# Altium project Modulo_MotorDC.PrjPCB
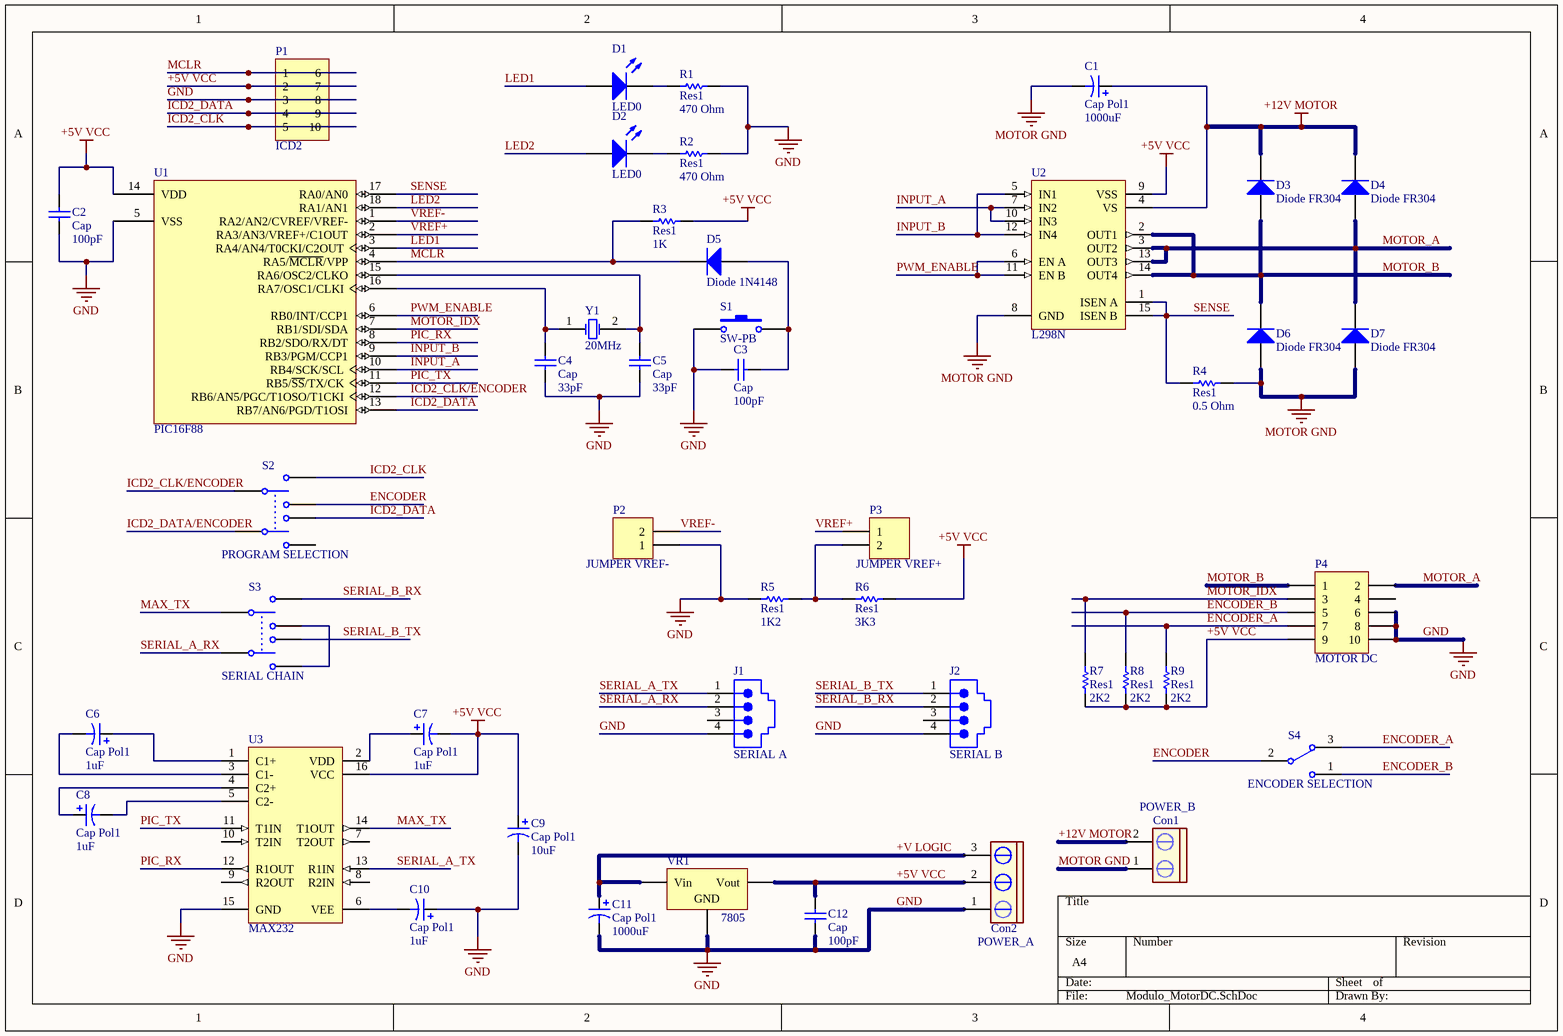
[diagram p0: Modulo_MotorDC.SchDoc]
1 sheet, 45 parts. Net scope: global (net labels, ports and power ports of the same name join across sheets).
Board file: Modulo_MotorDC.PcbDoc

## Sheet Modulo_MotorDC.SchDoc
size A4

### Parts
C1  Cap Pol1  value 1000uF  [RB5-10.5]
C2  Cap  value 100pF  [CAPR2.54-5.1x3.2]
C3  Cap  value 100pF  [CAPR2.54-5.1x3.2]
C4  Cap  value 33pF  [CAPR2.54-5.1x3.2]
C5  Cap  value 33pF  [CAPR2.54-5.1x3.2]
C6  Cap Pol1  value 1uF  [CAPPR2-5x6.8]
C7  Cap Pol1  value 1uF  [CAPPR2-5x6.8]
C8  Cap Pol1  value 1uF  [CAPPR2-5x6.8]
C9  Cap Pol1  value 10uF  [CAPPR2-5x6.8]
C10  Cap Pol1  value 1uF  [CAPPR2-5x6.8]
C11  Cap Pol1  value 1000uF  [RB5-10.5]
C12  Cap  value 100pF  [CAPR2.54-5.1x3.2]
Con1  POWER_B  [My_CN2]
Con2  POWER_A  [My_CN3]
D1  LED0  [LED-0]
D2  LED0  [LED-0]
D3  Diode FR304  [DIO18.84-9.6x5.6]
D4  Diode FR304  [DIO18.84-9.6x5.6]
D5  Diode 1N4148  [DIO7.1-3.9x1.9]
D6  Diode FR304  [DIO18.84-9.6x5.6]
D7  Diode FR304  [DIO18.84-9.6x5.6]
J1  SERIAL A  [15-43-6245]
J2  SERIAL B  [15-43-6245]
P1  ICD2  [HEADER10_5x2_B]
P2  JUMPER VREF-  [HDR1X2]
P3  JUMPER VREF+  [HDR1X2]
P4  MOTOR DC  [HEADER10_5x2_A]
R1  Res1  value 470 Ohm  [AXIAL-0.3]
R2  Res1  value 470 Ohm  [AXIAL-0.3]
R3  Res1  value 1K  [AXIAL-0.3]
R4  Res1  value 0.5 Ohm  [AXIAL-0.3]
R5  Res1  value 1K2  [AXIAL-0.3]
R6  Res1  value 3K3  [AXIAL-0.3]
R7  Res1  value 2K2  [AXIAL-0.3]
R8  Res1  value 2K2  [AXIAL-0.3]
R9  Res1  value 2K2  [AXIAL-0.3]
S1  SW-PB  [TS-063]
S2  PROGRAM SELECTION  [LD-202mini]
S3  SERIAL CHAIN  [LD-202mini]
S4  ENCODER SELECTION  [LD-202mini]
U1  PIC16F88  [PDIP300-P18]
U2  L298N  [Multiwatt15V]
U3  MAX232  [PE16A]
VR1  7805  [My_TO-220]
Y1  20MHz  [My_Crystal]

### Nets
+5V VCC: C2.2 C7.2 C9.1 C12.2 Con2.2 P1.2 P1.7 P4.9 R3.2 R6.2 R7.1 R8.1 R9.1 U1.14(VDD) U2.9(VSS) U3.16(VCC) VR1.3(Vout)
+12V MOTOR: C1.1 Con1.2 D3.2(K) D4.2(K) U2.4(VS)
GND: C2.1 C3.1 C4.1 C5.1 C9.2 C10.1 C11.2 C12.1 Con2.1 J1.4 J2.4 P1.3 P1.8 P2.1 P4.6 P4.8 P4.10 R1.2 R2.2 R5.1 S1.1 U1.5(VSS) U3.15(GND) VR1.2(GND)
MOTOR GND: C1.2 Con1.1 D6.1(A) D7.1(A) R4.2 U2.8(GND)
+V LOGIC: C11.1 Con2.3 VR1.1(Vin)
ENCODER: S2.3 S4.2
ENCODER_A: P4.7 R9.2 S4.3
ENCODER_B: P4.5 R8.2 S4.1
ICD2_CLK: P1.5 P1.10 S2.2
ICD2_CLK/ENCODER: S2.1 U1.12(RB6/AN5/PGC/T1OSO/T1CKI)
ICD2_DATA: P1.4 P1.9 S2.5 U1.13(RB7/AN6/PGD/T1OSI)
ICD2_DATA/ENCODER: S2.4
INPUT_A: U1.10(RB4/SCK/SCL) U2.7(IN2) U2.10(IN3)
INPUT_B: U1.9(RB3/PGM/CCP1) U2.5(IN1) U2.12(IN4)
LED1: D1.1(A) U1.3(RA4/AN4/T0CKI/C2OUT)
LED2: D2.1(A) U1.18(RA1/AN1)
MAX_TX: S3.1 U3.14(T1OUT)
MCLR: D5.2(K) P1.1 P1.6 R3.1 U1.4(RA5/~{MCLR}/VPP)
MOTOR_A: D4.1(A) D7.2(K) P4.2 U2.3(OUT2) U2.13(OUT3)
MOTOR_B: D3.1(A) D6.2(K) P4.1 U2.2(OUT1) U2.14(OUT4)
MOTOR_IDX: P4.3 R7.2 U1.7(RB1/SDI/SDA)
PIC_RX: U1.8(RB2/SDO/RX/DT) U3.12(R1OUT)
PIC_TX: U1.11(RB5/~{SS}/TX/CK) U3.11(T1IN)
PWM_ENABLE: U1.6(RB0/INT/CCP1) U2.6(EN_A) U2.11(EN_B)
SENSE: R4.1 U1.17(RA0/AN0) U2.1(ISEN_A) U2.15(ISEN_B)
SERIAL_A_RX: J1.2 S3.4
SERIAL_A_TX: J1.1 U3.13(R1IN)
SERIAL_B_RX: J2.2 S3.2
SERIAL_B_TX: J2.1 S3.5
VREF+: P3.1 U1.2(RA3/AN3/VREF+/C1OUT)
VREF-: P2.2 U1.1(RA2/AN2/CVREF/VREF-)
NetC3_2: C3.2 D5.1(A) S1.2
NetC4_2: C4.2 U1.16(RA7/OSC1/CLKI) Y1.1(OSC1)
NetC5_2: C5.2 U1.15(RA6/OSC2/CLKO) Y1.2(OSC2)
NetC6_1: C6.1 U3.1(C1+)
NetC6_2: C6.2 U3.3(C1-)
NetC7_1: C7.1 U3.2(VDD)
NetC8_1: C8.1 U3.4(C2+)
NetC8_2: C8.2 U3.5(C2-)
NetC10_2: C10.2 U3.6(VEE)
NetD1_2: D1.2(K) R1.1
NetD2_2: D2.2(K) R2.1
NetP3_2: P3.2 R5.2 R6.1
NetS3_3: S3.3 S3.6

Not connected (* = marked no-connect by the designer): J1 3; J2 3; P4 4; S2 6; U3 7(T2OUT) 8(R2IN) 9(R2OUT) 10(T2IN)

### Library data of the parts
C1 C6-C11 = Cap Pol1: Polarized Capacitor (Radial)
C2-C5 C12 = Cap: Capacitor
Con1 = CON2 pin blue: Connector blue screw
Con2 = CON3 pin Green: Connector green screw
D1 D2 = LED0: Typical INFRARED GaAs LED
D3 D4 D6 D7 = Diode 1N5404: 3 Amp General Purpose Rectifier
D5 = Diode 1N4148: High Conductance Fast Diode
J1 J2 = 15-43-6245: Right Angle, Standard Profile, RJ45-Keyed, Flange Mount PCB Jack; Ports: 1; Positions/Loaded: Port1 - 8 Keyed/4; PerformanceCategory: 3; PCB_Mounting: Thru-Hole; ComponentAvailability: Obsolete; DrillSize: Nominal, Rounded to nearest 0.05mm; PCB_Layout: Complies with Manufacturer's Recommendation.
P1 = Header 5X2A: Header, 5-Pin, Dual row
P2 P3 = Header 2: Header, 2-Pin
P4 = Header 5X2: Header, 5-Pin, Dual row
R1-R9 = Res1: Resistor
S1 = SW-PB: Switch
S2 S3 = SW-DPDT: Double-Pole, Double-Throw Switch
S4 = SW-SPDT: SPDT Subminiature Toggle Switch, Right Angle Mounting, Vertical Actuation
U1 = PIC16F88-E/P: Enhanced FLASH Microcontroller with nanoWatt Technology, 10-Bit A/D, 4K (x14-Bit words) FLASH, 368 Bytes RAM, 18-Pin PDIP, Standard VDD Range, Extended Temperature; Note: The CCP1 pin is determined by CCPMX in Configuration Word 1 register.
U2 = L298N: Dual Full Bridge Driver
U3 = MAX232ACPE: +5V Powered, Multi-Channel RS-232 Driver/Receiver
VR1 = Volt Reg: Voltage Regulator
Y1 = XTAL: Crystal Oscillator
